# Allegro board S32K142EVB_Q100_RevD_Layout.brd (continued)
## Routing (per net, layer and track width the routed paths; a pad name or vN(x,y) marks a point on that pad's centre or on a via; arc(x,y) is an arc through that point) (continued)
P3V3: length 28.6
  TOP w0.381: 42.32,31.17 C24.1 ; C24.1 42.32,30.53 ; C24.1 44.23,30.53 ; C24.1 44.23,31.17 ; C24.1 43.27,31.17 ; U15.5 39.68,34.61 ; U15.5 38.99,34.08 ; U15.5 38.99,35.15 ; J10.1 40.65,29.57 ; J10.1 39.57,28.49 ; J10.1 39.57,30.65 ; 40.09,34.71 C548.1 ; C548.1 40.18,34.29 ; C548.1 41.11,34.71 ; TS5.1 45.3,32.42 ; TS5.1 41.49,32.42 ; TS5.1 43.4,31.34 ; TS5.1 43.4,33.5
  TOP w0.635: TP510.1 J3.7
  L3_MIX w0.508: 34.74,4.34 J3.7 ; J3.7 36.3,5.9 ; J3.7 34.51,5.12 ; J3.7 34.74,5.9 ; J3.7 36.3,4.34 ; J3.7 35.52,6.13 ; 40.65,29.57 J10.1 39.57,28.49
P3V3_SDA: length 32.6
  TOP w0.178: U9.5 33.64,39.65 v1(33.64,39.64)
  TOP w0.203: R607.1 v1(8.72,53.38)
  TOP w0.254: U2.7 28.45,46.1 v1(28.2,45.85) 28.54,45.51 U4.1 ; 15.64,40.52 16.01,40.88 16.58,40.88 16.94,40.52 ; U8.1 v1(19.51,43.09) ; v1(30.04,45.2) 30.3,45.46 R15.1 ; U7.1 28.13,41.66 27.86,41.93 v1(27.83,41.93) ; 30.5,36.03 C19.1 31.01,35.52 ; v1(15.03,27.14) 14.52,27.14 14.44,27.06 R77.1 ; U1.1 9.04,50.33 ; C18.1 30.44,35.34 ; U8.11 v1(16.65,37.9) ; R1.2 v1(6.4,52.28) ; 9.19,49.94 C3.1 ; U10.1 v1(27.41,38.62) ; 30.51,37.11 R52.1 ; C26.1 17.92,28.09 J12.1 ; 9.19,50.89 R3.1
  TOP w0.508: 15.64,40.52 C12.1 13.52,40.52 13.17,40.17 R627.2 v1(12.41,39.29) ; R30.1 30.95,42.34 30.92,42.37 30.92,42.95 v1(30.91,42.95) ; R42.1 R39.2 37.61,41.46 C10.1 v1(37.61,42.64) ; R12.1 v1(25.56,46.72) ; R60.1 v1(11.75,37.33)
  TOP w0.635: v1(19.51,43.09) 18.65,43.95 C7.1 17.76,44.83 C6.1
  BOTTOM w0.254: 17.32,27.37 J12.1 18.65,28.09
  vias: v1(8.85,50.86) v1(30.38,36.71)
P5V0: length 134
  TOP w0.457: R56.1 44.41,12.36 TP509.1
  TOP w0.584: R95.2 R96.2 R97.2
  TOP w0.635: C22.1 C550.1 ; C22.1 34.76,35.09 35.78,36.11 R624.1 ; C22.1 R169.1 32.84,33.69 32.41,33.26 C21.1 28.46,33.26 TP527.1 ; v1(115.66,26.58) 116.8,25.44 116.8,21.37 119.34,18.83 R95.2
  L3_MIX w0.381: TP527.1 28.41,34.66 ; TP527.1 29.43,34.33 ; TP527.1 29.43,32.3 ; TP527.1 28.41,31.97 ; TP527.1 27.39,34.33 ; TP527.1 29.76,33.31 ; J10.3 34.49,30.65 ; J10.3 33.66,28.74 ; J10.3 33.66,30.39 ; J10.3 33.41,29.57 ; J3.9 38.84,4.34 ; J3.9 38.06,6.13 ; J3.9 39.08,5.12 ; J3.9 38.84,5.9
  BOTTOM w0.635: 28.41,31.97 TP527.1 29.76,33.31 ; 25.24,28.49 J107.2 ; J107.2 24.16,29.57 ; J107.2 25.24,30.65 ; J107.2 26.32,29.57 ; 33.41,29.57 J10.3 ; J10.3 34.49,28.49 ; J10.3 35.57,29.57 ; J10.3 34.49,30.65 ; 41.87,32.04 44.41,32.04 45.68,30.77 45.68,28.61 46.44,27.85 57.24,27.85 57.87,27.22 63.21,27.22 63.91,27.91 67.34,27.91 67.91,27.34 76.16,27.34 77.43,28.61 92.67,28.61 94.7,26.58 v1(115.66,26.58)
  vias: v1(40.6,25.9) v1(44.28,11.98)
P5V0_SDA_USB_CONN_VBUS: length 5.6
  TOP w0.152: 8.02,40.99 D17.2 7.34,41.45 7.34,41.44
  TOP w0.356: 5.64,42.72 J7.1
  TOP w0.381: L1.1 8.02,40.99
  TOP w0.635: 7.34,41.44 6.92,41.44 5.64,42.72
P5V_SBC: length 85.9
  TOP w0.203: U33.1 v1(47.97,22.52) R617.1 ; v1(37.3,19.6) R621.1 U34.1 ; 42.89,22.64 43.01,22.52 U32.1
  TOP w0.254: R622.1 41.74,17.7 v1(42.13,18.08) R576.1 ; 42.38,21.88 R562.1 ; R562.1 42.89,22.39 ; R562.1 41.87,22.39 ; 41.24,22.26 41.24,22.77 ; 41.24,22.77 41.75,22.77 ; 41.24,22.77 40.73,22.77 ; 36.41,24.93 R619.1 ; R619.1 37.43,24.93 ; R619.1 36.92,25.44 ; 42,24.55 R572.1 ; 37.62,24.68 U26.1 ; 21.57,17.74 U19.5
  TOP w0.305: R536.1 v1(12.53,21.63) ; v1(20.66,14.57) 21.09,14.14 C27.1 21.98,15.18 22.82,16.01 C547.1 21.62,17.69 21.57,17.74
  TOP w0.508: TP525.1 53.05,21.12 R618.1 ; TP525.1 R571.1 TS8.1 ; TP525.1 v1(52.03,21.5)
  TOP w0.635: J107.1 25.36,27.15 v1(25.36,22.66) 24.16,21.45 R535.1 22.14,21.45 R594.1
  L3_MIX w0.254: v1(43.01,21.76) 42.66,21.4 42.66,21.35 42.13,20.82 v1(42.13,18.08)
  L3_MIX w0.305: v1(12.53,21.63) 16.73,21.63 17.23,21.12 17.23,14.87 17.54,14.57 v1(20.66,14.57)
  L3_MIX w0.635: v1(25.36,22.66) 22.56,22.66 19.52,25.69 13.17,25.69 12.53,25.06 v1(12.53,21.63)
  BOTTOM w0.254: v1(42.13,18.08) 41.61,17.56 38.32,17.56 37.3,18.58 v1(37.3,19.6)
  BOTTOM w0.508: J107.1 28.86,29.57 ; J107.1 27.78,28.49 ; J107.1 27.78,30.65
  vias: v1(34.58,24.56)
P5V_SDA: length 24.5
  TOP w0.254: 22.16,45.36 R14.1 22.67,45.86 ; U8.6 16.74,41.43 v1(16.62,41.43)
  TOP w0.508: C15.1 7.5,37.47 7.18,37.79 v1(7.18,38.88) L1.2 ; R70.1 v1(8.14,31.06) ; C11.1 v1(9.35,38.48) ; R57.1 v1(26.57,37.38) ; U11.1 v1(8.08,31.93) ; C25.1 v1(8.15,29.82)
  L3_MIX w0.635: v1(16.62,41.43) v1(16.62,45.82)
  BOTTOM w0.254: v1(22.02,45.89) 22.47,45.44 22.47,39.84 23.1,39.21 24.74,39.21 25.5,38.45 25.53,38.45 25.9,38.08 25.9,38.05 v1(26.57,37.38)
  vias: v1(7.36,46.09) v1(8.23,46.11) v1(9.16,46.11)
P5V_SDA_PSW: length 26.3
  TOP w0.584: U11.6 8.08,34.7 7.84,34.46 v1(6.95,34.46)
  BOTTOM w0.584: J107.3 19.08,25.95 9.49,25.95 6.95,28.49 v1(6.95,34.46)
VBATT: length 94.6
  TOP w0.254: D9.A 28.75,13.22 ; D9.A 28.75,10.73 ; D9.A 29.64,11.98 ; D9.A 27.86,11.98 ; C544.1 25.87,10.07 ; C544.1 25.87,9.05 ; C544.1 25.36,9.56 ; J3.1 27.9,6.13 ; J3.1 28.92,5.12 ; J3.1 26.89,5.12 ; J16.1 22.29,11.8 ; J16.1 22.29,7.96 ; J16.1 23.2,9.88 ; 24.85,12.99 TP522.1 ; TP522.1 26.89,12.99 ; TP522.1 26.89,10.96 ; TP522.1 25.87,13.32 ; TP522.1 24.85,10.96 ; TP522.1 25.87,10.63 ; TP522.1 24.52,11.98 ; TP522.1 27.22,11.98
  TOP w0.635: J3.15 TP507.1 44.41,8.29 43.01,9.69 30.44,9.69 29.81,10.33 ; R606.2 v1(9.61,18.2)
  L3_MIX w1.016: v1(9.61,18.2) 5.8,14.38 5.42,14.38 v1(4.79,13.75)
  BOTTOM w1.016: v3(23.93,7.2) 12.91,7.2 11.23,8.89 9.65,8.89 v1(4.79,13.75) 4.79,31.31 J11.2
VDD: length 85.1
  TOP w0.381: TPAD99.1 47.65,26.84 ; TPAD99.1 47.55,27.3 ; TPAD99.1 46.51,26.84 ; TPAD99.1 46.61,26.37 ; TPAD99.1 46.61,27.3 ; TPAD99.1 47.08,26.26 ; TPAD99.1 47.55,26.37 ; TPAD99.1 47.08,27.41 ; TP511.1 54.15,32.89 ; TP511.1 53.22,31.96 ; TP511.1 53.11,32.42 ; TP511.1 53.68,33 ; TP511.1 54.25,32.42 ; TP511.1 53.22,32.89 ; 48.81,29.58 J15.2 ; J15.2 49.88,28.51 ; J15.2 49.88,30.64 ; J15.2 50.94,29.58 ; J14.1 54.49,39.29 ; J14.1 54.49,38.57 ; J14.1 53.16,38.57 ; 49.11,37.25 R121.1 ; R121.1 49.2,36.83 ; R121.1 49.62,36.74 ; R121.1 50.04,36.83 ; R121.1 50.13,37.25 ; 47.71,44.87 R623.1 ; R623.1 47.8,45.29 ; R623.1 48.22,44.36 ; R623.1 47.8,44.45 ; C552.1 53.17,37.38 ; C552.1 53.68,36.87 ; C552.1 53.6,36.44 ; C552.1 53.6,37.29 ; C552.1 53.17,36.36 ; 40.46,37.55 SH1.2 ; SH1.2 41.15,38.15 ; SH1.2 40.46,38.74 ; 47.8,46.31 R574.1 ; R574.1 47.8,45.46 ; R574.1 47.71,45.89 ; 50.7,33.44 TS1.1 ; TS1.1 52.86,33.44 ; TS1.1 51.78,31.53 ; TS1.1 51.78,35.34 ; TP9.1 44.48,36.83 ; TP9.1 42.12,37.85 ; TP9.1 44.15,37.85 ; TP9.1 43.13,38.18 ; TP9.1 41.79,36.83 ; 47.8,41.23 R573.1 ; R573.1 47.71,40.81 ; R573.1 47.8,40.38 ; R573.1 48.22,41.31
  TOP w0.406: 49.49,34.33 R593.1 50.25,33.57 ; 50.25,32.04 R117.1 49.49,31.28
  TOP w0.508: SW3.4 v1(124.13,19.63) ; SW3.2 v1(124.13,27.21) ; SW2.4 v1(124.13,30.97) ; SW2.2 v1(124.13,38.79)
  TOP w0.635: v1(45.68,14.64) 45.68,16.29 R604.1
  L3_MIX w0.508: 42.12,35.81 TP9.1 ; TP9.1 43.13,35.48 ; TP9.1 42.12,37.85 ; TP9.1 41.79,36.83 ; TP9.1 43.13,38.18 ; 35.95,29.57 J10.2 37.03,30.65
  L3_MIX w0.635: 47.97,2.96 47.97,6.52 45.55,8.93 45.55,11.09 45.68,11.21 v1(45.68,14.64)
  BOTTOM w0.381: 112.94,56.88 TP4.1 ; TP4.1 112.94,54.85 ; TP4.1 115.3,55.87 ; TP4.1 112.61,55.87 ; TP4.1 114.97,56.88 ; TP4.1 113.96,54.52 ; TP4.1 114.97,54.85
  vias: v1(69.96,3.11) v1(69.97,2.07) v1(69.94,1.09) v1(70.67,3.09) v1(70.66,2.06) v1(70.64,1.12)
VDD_MCU: length 63.8
  TOP w0.254: C140.1 64.61,33.06 ; C140.1 64.1,32.55 ; C140.1 63.59,33.06 ; C144.1 62.71,33.49 ; C144.1 62.71,32.85 ; C144.1 60.81,32.85 ; C144.1 61.76,32.85 ; U35.10 68.64,30.56 ; U35.10 68.64,30.66 ; U35.10 66.6,30.75 ; U35.10 66.6,30.66 ; U35.61 81.54,28.16 ; 59.27,35.47 R300.1 ; R300.1 59.27,34.84 ; R300.1 60.03,35.47 ; R300.1 60.8,34.84
  TOP w0.305: U35.87 v1(75.87,38.39) 75.87,38.94 C129.1 ; 84.59,28.31 84.24,28.31 84.09,28.16 U35.61 ; U35.38 75.37,19.88 v2(75.4,19.85)
  TOP w0.635: J15.1 47.34,31.28 47.97,31.92 R117.2 ; C133.1 76.42,41.19 75.65,40.42 C142.1 C129.1 ; TS2.1 75.65,15.53 C131.1 C141.1 75.65,19.6 v2(75.4,19.85) ; 81.54,28.16 v2(75.12,28.16) ; 84.59,28.31 C143.1 87.92,28.31 C146.1 88.1,28.49 TP533.1
  BOTTOM w0.508: v1(68.92,30.52) 67.53,31.92 v2(64.99,31.92)
  BOTTOM w0.635: v2(64.99,31.92) 64.35,31.28 49.04,31.28 J15.1
  vias: v2(75.12,30.66)
VDD_PERH: length 207.4
  TOP w0.16: R648.1 R647.1 90.51,43.42 84,49.94 84,50.75 82.38,52.36 82.38,54.78 J6.10 ; U32.8 43.88,23.69 v1(43.54,24.04)
  TOP w0.203: v1(38.27,19.85) 38.27,19.93 38.44,20.1 38.7,20.1 38.8,20 U34.8 ; R614.1 41.62,21.63 41.87,21.37 41.87,21.35 v1(41.93,21.35) ; R615.1 v1(37.44,21.63) ; v1(48.86,24.17) 49.06,24.17 49.47,23.75 U33.8 ; v1(37.55,26.2) 38.19,26.2 38.55,25.84 U26.8 ; R616.1 v1(43.27,26.71) 43.01,26.45 R612.1
  TOP w0.381: 53.56,12.8 TS6.1 ; TS6.1 53.56,14.96 ; TS6.1 51.65,13.88
  TOP w0.508: R610.1 47.84,24.55 48.22,24.17 v1(48.86,24.17) ; R610.1 47.08,24.93 46.7,25.31 R609.1 ; R610.1 47.84,25.63 49.05,26.84 51.55,26.84 51.9,26.48 R611.1
  TOP w0.635: v2(65.49,12.48) 60.03,12.48 59.02,13.5 v1(55.97,13.5) ; v1(48.09,34.71) 47.97,34.58 R593.2 ; v1(37.55,26.2) 36.66,26.2 36.41,26.45 R613.1 35.84,27.22 TP541.1 R570.1 R530.1 R538.1 v1(34.76,22.9) ; J3.3 30.44,6.64 30.24,6.85 C49.1
  L3_MIX w0.635: v2(65.49,12.48) 66.26,12.48 67.34,11.4 67.34,9.12 70.57,5.88 70.57,4.36 71.72,3.21 71.72,1.82 72.35,1.18 82.38,1.18 J5.10 ; v1(43.27,26.71) 43.27,24.31 v1(43.54,24.04) ; v1(48.86,24.17) 48.86,26.58 51.25,28.97 51.25,31.56 v1(48.09,34.71) ; J3.3 30.19,5.37 30.19,20.1 32.98,22.9 v1(34.76,22.9) ; v1(38.27,19.85) 38.27,20.99 37.64,21.63 v1(37.44,21.63) 37.44,23.55 37.55,23.66 v1(37.55,26.2) ; v1(55.33,20.99) 54.83,20.49 54.83,16.17 v1(55.97,15.02) v1(55.97,14.26) v1(55.97,13.5)
  BOTTOM w0.381: J5.10 84.8,2.58 ; J5.10 84.22,3.59 ; J5.10 84.56,3.36 ; J5.10 83.78,3.59 ; J5.10 82.77,2.14 ; J5.10 84.8,3.02 ; J5.10 83,3.36 ; J5.10 82.77,2.58 ; J6.10 82.02,55.14 ; J6.10 81.24,56.93 ; J6.10 80.46,55.14 ; J6.10 82.02,56.7 ; J6.10 82.26,55.92 ; J6.10 81.24,54.9 ; J6.10 80.8,54.9 ; J6.10 80.46,56.7 ; R13.1 120.84,49.8 ; R13.1 120.84,47.77 ; R13.1 121.85,48.78 ; R13.1 119.82,48.78 ; 104.48,54.44 TP526.1 ; TP526.1 104.48,57.14 ; TP526.1 105.5,56.81 ; TP526.1 103.47,54.78 ; TP526.1 103.47,56.81 ; TP526.1 103.14,55.79 ; TP526.1 105.83,55.79 ; TP526.1 105.5,54.78
  BOTTOM w0.508: v1(41.93,21.35) 38.57,21.35 38.29,21.63 v1(37.44,21.63) 36.99,22.08 36.99,22.19 36.28,22.9 v1(34.76,22.9)
  BOTTOM w0.635: v1(37.55,26.2) 38.95,24.8 41.36,24.8 41.49,24.93 42.9,24.93 43.54,24.3 v1(43.54,24.04) 44.23,24.04 44.36,24.17 v1(48.86,24.17) 53.15,24.17 55.33,21.98 v1(55.33,20.99)
VDDA: length 18.2
  TOP w0.305: U35.11 66.11,30.16
  TOP w0.381: 60.03,32.68 R300.2 59.27,33.31 ; C540.1 64.1,31.53 ; C540.1 63.59,32.04 ; C540.1 63.17,31.96 ; 58.84,33.31 L512.1 ; L512.1 58.42,33.4 ; L512.1 59.26,34.24 ; L512.1 58.33,33.82 ; L512.1 58.42,34.24 ; C543.1 61.3,32.04 ; C543.1 61.73,31.96 ; C543.1 60.88,31.96 ; C543.1 60.79,31.53 ; C539.1 58.71,31.34 ; C539.1 58.08,33.25 ; C539.1 58.71,32.3 ; 62.02,31.96 C541.1 ; C541.1 62.45,32.04 ; C541.1 62.87,31.96 ; 58.84,30.39 C542.1 58.84,31.34 ; 64.6,30.9 R628.1 65.37,30.9
  TOP w0.508: R628.1 65.48,30.16 66.11,30.16
ADC_POT: length 72.2
  TOP w0.16: C549.1 R597.2 TP528.1 115.02,48.55 99.15,48.55 97.5,46.9 v1(97.5,38.14) ; R164.1 v1(79.46,14.64) ; R665.1 v1(88.73,38.14)
  L3_MIX w0.16: v1(86.45,15.41) 86.45,21.95 86.83,22.33 86.83,23.44 87.21,23.82 87.21,24.42 88.35,25.57 88.35,26.07 87.46,26.96 87.46,36.87 v1(88.73,38.14)
  BOTTOM w0.16: v1(79.46,14.64) 82.13,14.64 82.89,15.41 v1(86.45,15.41) ; v1(97.5,38.14) v1(88.73,38.14)
AREF: length 57.4
  TOP w0.635: v1(58.76,43.35) 58.76,43.6 54.19,48.17 40.35,48.17 38.82,46.65 36.28,46.65 33.62,49.31 25.36,49.31 23.84,50.84 J2.15 ; R569.2 v1(59.54,29.25)
  L3_MIX w0.635: v1(58.76,43.35) 58.76,29.88 59.4,29.25 v1(59.54,29.25)
BTN0: length 47
  TOP w0.16: C16.1 119.63,31.03 R596.2 TP530.1 114.13,28.11 99.95,28.11 94.58,22.73 94.58,18.2 89.33,12.95 86.49,12.95 84.67,14.77 R152.1
BTN1: length 47.6
  TOP w0.16: C28.1 119.71,27.34 R595.2 TP529.1 100.04,27.34 95.21,22.52 95.21,16.8 91.02,12.61 85.94,12.61 R153.1
CAN_HI: length 23.4
  TOP w0.16: U19.18 14.82,16.74 v1(14.44,16.36) ; R92.1 TP504.1 ; R92.1 v1(8.85,23.28) ; R92.1 5.55,23.28 5.51,23.24 J13.1
  L3_MIX w0.16: v1(8.85,23.28) 9.36,23.28 11.9,20.74 15.46,20.74 16.47,19.72 16.47,17.82 15.01,16.36 v1(14.44,16.36)
CAN_LO: length 22.1
  TOP w0.16: J13.2 4.2,20.7 4.53,20.36 4.53,15.02 6.18,13.37 7.33,13.37 7.33,14.39 10.18,17.24 TP503.1 U19.17
JTAG_TCLK/SWD_CLK: length 59
  TOP w0.16: J14.4 50.54,40.56 49.76,39.79 R575.1 v1(49.24,39.03) ; v1(69.43,45.3) TP536.1 69.18,44.23 69.18,43.09 ; R626.1 v1(28.03,35.09)
  L3_MIX w0.16: v1(49.24,39.03) 49.24,36.87 v1(48.73,36.36)
  BOTTOM w0.16: v1(48.73,36.36) 46.06,36.36 43.65,38.77 41.36,38.77 38.82,36.23 34.25,36.23 33.11,35.09 v1(28.03,35.09) ; J14.4 50.52,40.56 50.25,40.3 50.25,39.2 51.29,38.16 55.99,38.16 61.85,44.03 68.72,44.03 69.43,44.74 v1(69.43,45.3)
JTAG_TDI: length 30.1
  TOP w0.16: J14.8 51,43.1 R623.2 ; 71.21,43.09 71.21,44.36 TP538.1 v1(71.08,45.38)
  BOTTOM w0.16: J14.8 50.75,43.1 50.38,43.47 50.38,44.87 51.4,45.89 70.57,45.89 v1(71.08,45.38)
JTAG_TDO: length 34.8
  TOP w0.16: J14.6 50.27,41.83 R573.2 ; v1(73.37,45.3) 73.37,44.53 TP537.1 73.24,44.4 73.24,43.09
  BOTTOM w0.16: v1(73.37,45.3) 72.4,46.27 51.27,46.27 49.62,44.62 49.62,42.58 50.37,41.83 J14.6
JTAG_TMS/SWD_DIO_PTA4: length 45.6
  TOP w0.16: J14.2 51.28,39.29 50.25,38.27 R121.2 v1(48.7,38.27) ; 67.91,43.09 67.91,44.36 TP535.1 v1(66.97,44.49) ; v1(34.12,47.54) 33.74,47.92 R625.1
  BOTTOM w0.16: J14.2 52.68,38.5 55.83,38.5 61.56,44.23 61.58,44.23 61.71,44.36 66.84,44.36 v1(66.97,44.49) ; v1(48.7,38.27) 47.71,38.27 42.51,43.47 34.89,43.47 33.62,44.74 33.62,47.03 v1(34.12,47.54)
LEDRGB_BLUE: length 4.4
  TOP w0.16: Q8.3 118.75,7.4 118.83,7.48 TP28.1 D11.C3
LEDRGB_GREEN: length 7.5
  TOP w0.16: Q7.3 118.9,4.86 TP29.1 D11.C2
LEDRGB_RED: length 10.6
  TOP w0.16: Q6.3 118.71,2.58 TP30.1 D11.C1
LIN: length 34.1
  TOP w0.406: U21.6 14.46,25.43 13.18,26.71 TS4.1 11.14,25.9 R171.1 R80.1 8.6,24.75 7.92,25.43 TP18.1 5.51,26.03 C17.1 J11.1
LIN_RX: length 89.8
  TOP w0.16: v1(71.21,18.96) 70.7,18.45 R650.2 ; R538.2 31.44,22.9 31.44,22.89 v1(31.2,22.89) U21.1 ; R130.1 TP519.1 v1(68.54,12.74) 70.45,12.74 70.7,12.48 72.48,12.48 73.2,11.76 85.33,11.76 85.66,11.43 v1(86.19,11.43) ; R667.1 v1(88.61,23.03)
  L3_MIX w0.16: v1(88.61,23.03) 87.34,21.76 87.34,15.02 86.19,13.88 v1(86.19,11.43) ; v1(66.76,20.87) 67.4,20.87 69.3,18.96 v1(71.21,18.96) 68.54,16.29 v1(68.54,12.74)
  BOTTOM w0.16: v1(66.76,20.87) 66.76,20.45 65.82,19.51 59.6,19.51 58.92,20.19 51.31,20.19 50.38,21.12 42.89,21.12 42.13,21.88 38.82,21.88 37.3,23.41 36.5,23.41 36.5,23.41 34.55,23.41 34.54,23.41 31.72,23.41 v1(31.2,22.89)
LIN_SLP: length 52.8
  TOP w0.16: R529.2 61.19,18.45 TP521.1 50.84,17.26 ; R530.2 31.44,24.42 v1(31.18,24.16) U21.2
  TOP w0.203: 50.84,17.26 50.51,16.93 49.75,16.93 48.86,17.82 v1(48.37,17.82)
  L3_MIX w0.203: v1(31.18,24.16) 30.44,24.16 24.73,18.45 v1(24.73,18.2)
  BOTTOM w0.203: v1(48.37,17.82) 46.85,16.29 37.55,16.29 35.52,18.33 25.34,18.33 25.21,18.2 v1(24.73,18.2)
LIN_TX: length 88
  TOP w0.16: U21.4 v1(31.2,26.7) 31.44,26.7 31.44,26.71 R570.2 ; v1(87.21,10.71) 86.87,10.37 78.11,10.37 77.39,11.08 76.45,11.08 76.08,10.7 69.18,10.7 v1(67.14,12.74) 66.51,13.37 TP520.1 R131.1 ; R668.1 v1(88.61,20.74) ; R652.2 v1(68.8,18.33)
  L3_MIX w0.16: v1(88.61,20.74) 88.1,20.23 88.1,14.39 87.72,14.01 87.72,13.25 87.21,12.74 v1(87.21,10.71) ; v1(67.14,12.74) 67.14,16.04 68.8,17.69 v1(68.8,18.33) 67.15,19.97 v1(65.63,19.97)
  BOTTOM w0.16: v1(65.63,19.97) 60.37,19.97 55.45,24.89 45.8,24.89 45.79,24.89 44.81,24.89 44.81,24.89 43.88,24.89 43.48,25.28 43.48,25.29 43.26,25.51 41.18,25.51 41.11,25.44 39.13,25.44 37.79,26.78 37.32,26.78 37.24,26.7 v1(31.2,26.7)
LVLRST_EN: length 2.1
  TOP w0.203: U1.5 5.95,50.33 5.57,50.71 R1.1
MIC2005_CSLEW: length 1.8
  TOP w0.16: U11.5 C15.2
POWER_EN: length 15.7
  TOP w0.16: R69.1 v1(12.64,32.91) ; U8.31 20.95,42.91 v1(20.95,42.96)
  BOTTOM w0.16: v1(12.64,32.91) 12.64,34.08 15.65,37.09 15.65,38.42 16.73,39.5 17.25,39.5 20.38,42.63 20.63,42.63 v1(20.95,42.96)
PTA0: length 50.6
  TOP w0.16: v1(87.73,41.81) 87.73,40.69 86.58,39.54 84.87,39.54 84.65,39.31 82.41,39.31 81.84,38.73 80.57,38.73 79.87,38.04 U35.79
  L3_MIX w0.16: J5.7 82.19,6.06 82.19,6.85 85.18,9.85 85.18,16.48 85.85,17.16 85.85,23.45 86.45,24.04 86.45,38.38 86.65,38.57 86.86,38.79 86.86,40.95 v1(87.73,41.81)
PTA1: length 40.8
  TOP w0.16: R666.1 v1(88.73,39.15)
  L3_MIX w0.16: v1(86.07,38.65) 86.07,37.39 85.48,36.81 85.48,35.62 85.69,35.41 85.69,24.34 85.18,23.84 85.18,17.44 84.5,16.76 84.5,10.15 81.62,7.28 80.86,7.28 J5.5
  BOTTOM w0.16: v1(86.07,38.65) 86.58,39.15 v1(88.73,39.15)
PTA2: length 6.3
  TOP w0.16: U35.73 85.26,34.16 86.19,35.09 R644.1 R542.2 R540.1
PTA3: length 9
  TOP w0.16: U35.72 85.3,33.66 86.11,34.47 88.88,34.47 89.5,35.09 89.5,37.12
PTA4: length 1
  TOP w0.16: R546.1 66.89,43.09
PTA6: length 4.4
  TOP w0.16: U35.58 84.09,26.66 85.69,25.06 R147.1
PTA7: length 31.3
  TOP w0.16: U35.57 83.91,26.16 v1(84.42,25.65)
  L3_MIX w0.16: J5.9 85.36,6.7 86,6.7 89.04,9.74 89.04,11.61 89.99,12.57 89.99,13.57 90.08,13.66 90.08,15.98 89.95,16.11 89.95,25.64 v1(90,25.69)
  BOTTOM w0.16: v1(90,25.69) 89.37,26.33 85.1,26.33 v1(84.42,25.65)
PTA8: length 18.1
  TOP w0.16: U35.100 v1(69.37,38.38)
  L3_MIX w0.16: v1(69.37,38.38) 69.37,38.83 68.29,39.92 68.29,43.47 69.05,44.23 69.05,45.03 68.97,45.11 68.97,47.84 71.08,49.95 J6.17
PTA9: length 20.1
  TOP w0.16: U35.99 v1(69.87,35.64)
  L3_MIX w0.16: v1(69.87,35.64) 69.87,37.19 68.91,38.15 68.91,38.79 67.91,39.79 67.91,44.74 68.54,45.38 J6.19
PTA10: length 1
  TOP w0.16: 74.26,43.09 R545.1
PTA11: length 33.5
  TOP w0.16: U35.91 73.87,38.02 73.41,38.48 73.41,39.07 73.41,39.07 73.41,39.09 73.68,39.36 73.7,39.36 73.87,39.53 v1(73.87,41.19)
  L3_MIX w0.16: J1.2 62.17,54.63 62.17,51.98 61.56,51.37 v1(61.56,41.06)
  BOTTOM w0.16: v1(61.56,41.06) 62.19,41.69 71.57,41.69 72.1,41.17 72.1,41.17 72.54,40.73 73.41,40.73 v1(73.87,41.19)
PTA12: length 21.6
  TOP w0.16: U35.90 74.37,38.15 73.88,38.65 v1(73.88,38.9)
  L3_MIX w0.16: v1(73.88,38.9) 74.37,39.39 74.37,43.71 75.48,44.82 75.48,49.36 72.53,52.32 72.53,54.82 J6.16
PTA13: length 20.3
  TOP w0.16: v1(74.76,38.39) 74.87,38.29 U35.89
  L3_MIX w0.16: v1(74.76,38.39) 74.76,43.47 75.82,44.52 75.82,51.66 75.07,52.42 75.07,54.82 J6.14
PTA14: length 67
  TOP w0.16: v1(75.02,47.54) 75.8,46.76 75.8,41.43 75.02,40.65 75.02,38.9 75.37,38.55 U35.88
  BOTTOM w0.16: v1(75.02,47.54) 64.48,47.54 63.38,48.64 53.41,48.64 52.18,49.86 39.74,49.86 38.72,50.88 27.33,50.88 25.14,53.06 25.14,54.62 J2.16
PTA15: length 7.4
  TOP w0.16: R167.1 81.57,41.56 81.57,40.38 81.3,40.11 79.86,40.11 77.87,38.12 U35.83
PTA16: length 7.6
  TOP w0.16: U35.82 78.37,38.06 80.08,39.77 81.44,39.77 82.77,41.1 82.77,41.59 R165.1
PTA17: length 54.1
  TOP w0.16: U35.62 82.07,28.66 v1(81.03,29.69)
  L3_MIX w0.16: J1.4 59.63,54.63 59.63,52.73 58,51.09 58,29.5 59.02,28.49 v1(59.52,28.49)
  BOTTOM w0.16: v1(81.03,29.69) 60.73,29.69 v1(59.52,28.49)
PTB0: length 50.8
  TOP w0.16: J4.5 61.47,10.75 68.63,10.75 69.01,10.37 76.22,10.37 76.59,10.74 77.25,10.74 77.97,10.03 87.25,10.03 v1(87.59,9.69) ; R670.1 v1(88.61,24.04)
  L3_MIX w0.16: v1(87.59,9.69) 87.79,9.89 87.79,12.56 88.1,12.87 88.1,13.88 88.48,14.26 88.48,19.85 89.12,20.49 89.12,23.53 v1(88.61,24.04)
PTB1: length 45.4
  TOP w0.16: R669.1 v1(88.61,21.76) ; J4.7 63.67,10.41 68.49,10.41 68.87,10.03 76.36,10.03 76.73,10.41 77.11,10.41 77.83,9.69 85.68,9.69 v1(86.32,9.05)
  L3_MIX w0.16: v1(88.61,21.76) 87.72,20.87 87.72,14.77 86.7,13.75 86.7,13.61 86.7,13.6 86.7,13.22 86.7,13.22 86.7,11.21 86.32,10.83 v1(86.32,9.05)
PTB2: length 83.8
  TOP w0.16: v1(79.51,48.51) 79.12,48.91 72.66,48.91 72.04,49.52 39.36,49.52 38.34,50.54 31.76,50.54 J2.11 ; U35.48 v1(80.37,19.63)
  L3_MIX w0.16: v1(80.37,19.63) 80.37,23.68 79.8,24.25 79.8,28.88 79.31,29.37 79.31,46.74 79.51,46.94 v1(79.51,48.51)
PTB3: length 78.1
  TOP w0.16: v1(78.96,50.2) 39.64,50.2 38.62,51.22 33.62,51.22 J2.9 ; U35.47 79.89,21.42 v1(79.89,22.84)
  L3_MIX w0.16: v1(78.96,50.2) 78.83,50.08 78.83,47.9 78.97,47.76 78.97,29.23 79.46,28.74 79.46,23.27 v1(79.89,22.84)
PTB4: length 66.7
  TOP w0.16: J2.7 35.48,51.89 38.9,51.89 39.92,50.88 67.57,50.88 v1(67.78,51.09) ; v1(69.06,24.9) 70.37,23.59 U35.28
  L3_MIX w0.16: v1(67.78,51.09) 67.78,45.12 67.5,44.84 67.5,39.69 68.54,38.65 68.54,38.01 69.41,37.14 69.41,35.11 70.02,34.5 70.02,25.85 v1(69.06,24.9)
PTB5: length 75.1
  TOP w0.16: v1(63.21,16.04) 63.21,16.68 64.48,17.95 65.87,17.95 67.69,19.76 69.45,19.76 69.87,20.18 U35.27
  L3_MIX w0.16: v1(43.9,13.37) 44.16,13.63 44.16,25.68 43.95,25.88 43.95,29.67 44.58,30.31 44.58,32.69 44.58,32.69 44.58,32.76 45.43,33.6 45.43,44.49 J2.5
  BOTTOM w0.16: v1(63.21,16.04) 62.32,15.15 59.4,15.15 57.29,13.04 44.24,13.04 v1(43.9,13.37)
PTB6: length 6.4
  TOP w0.16: R81.1 R84.1 63.32,25.95 65.03,27.66 U35.16
PTB6_XTAL: length 7.2
  TOP w0.16: Y3.2 57.48,25.58 C127.1 58.76,25.06 59.52,25.82 R91.2 60.29,25.82 60.54,26.07 61.81,26.07 R84.2
PTB7: length 6.2
  TOP w0.16: R90.1 R88.1 63.72,26.96 64.84,28.09 65.76,28.09 65.83,28.16 U35.15
PTB7_EXTAL: length 7.2
  TOP w0.16: R88.2 61.18,26.96 60.79,27.34 R91.1 59.52,27.34 58.76,28.11 C126.1 57.48,27.58 Y3.1
PTB8: length 44.7
  TOP w0.16: U35.77 80.87,37.72 81.16,38.01 83.53,38.01 83.91,38.39 84.54,38.39 84.54,38.39 v1(84.54,38.39)
  L3_MIX w0.16: v1(85.21,49.6) 85.21,44.79 84.89,44.47 84.89,38.73 v1(84.54,38.39)
  BOTTOM w0.16: v1(85.21,49.6) 75.5,49.6 74.51,50.58 61.9,50.58 60.37,52.12 59.64,52.12 J1.5
PTB9: length 46.6
  TOP w0.16: v1(84.22,36.54) 83.86,36.91 U35.76
  L3_MIX w0.16: v1(84.41,48.88) 83.78,48.26 83.78,44.1 84.54,43.35 84.54,39.15 84.08,38.69 84.08,38.2 84.22,38.06 v1(84.22,36.54)
  BOTTOM w0.16: J1.7 59.02,50.2 74.41,50.2 75.36,49.26 84.03,49.26 v1(84.41,48.88)
PTB10: length 48.8
  TOP w0.16: v1(83.12,35.85) 83.02,35.85 83.12,35.75 U35.75
  L3_MIX w0.16: v1(55.08,34.96) 55.08,34.96 55.08,34.97 55.08,47.85 53.3,49.63 J1.9
  BOTTOM w0.16: v1(55.08,34.96) 55.08,34.96 55.08,34.96 55.24,34.8 63.43,34.8 64.82,36.2 82.78,36.2 v1(83.12,35.85)
PTB11: length 55.8
  TOP w0.16: U35.74 v1(84.49,34.66)
  L3_MIX w0.16: J1.11 50.76,50.04 54.62,46.18 54.62,34.77 54.89,34.5 54.91,34.5 54.94,34.46 v1(54.94,32.27)
  BOTTOM w0.16: v1(54.94,32.27) 63.85,32.27 66.75,35.18 70.15,35.18 70.83,35.86 79.76,35.86 80.15,35.47 81.86,35.47 82.68,34.66 v1(84.49,34.66)
PTB12: length 81.8
  TOP w0.16: v1(92.42,34.2) 91.67,33.46 86.74,33.46 84.94,31.66 U35.68
  L3_MIX w0.16: J4.3 53.05,5.37 53.05,21.28 53.26,21.49 53.26,22.09 54.32,23.15 54.32,29.91 54.15,30.07 54.15,30.43 54.32,30.6 54.32,34.6 54.06,34.85 v1(54.06,35.9)
  BOTTOM w0.16: v1(92.42,34.2) 92.29,34.07 88.51,34.07 86.86,35.73 83.91,35.73 83.1,36.53 64.14,36.53 63.78,36.17 63.78,36.15 63.48,35.85 63.06,35.85 63.01,35.9 v1(54.06,35.9)
PTB13: length 40.1
  TOP w0.16: U35.67 v1(84.41,31.16)
  L3_MIX w0.16: J5.11 86.32,6.01 87.21,6.9 87.72,6.9 90.77,9.95 90.77,11.81 92.72,13.75 92.72,17.32 92.72,17.33 92.72,17.61 93.31,18.2 93.31,30.9 v1(93.69,31.28)
  BOTTOM w0.16: v1(93.69,31.28) 87.72,31.28 87.59,31.16 v1(84.41,31.16)
PTB14: length 58.3
  TOP w0.16: R637.1 v1(88.73,32.93)
  L3_MIX w0.16: v1(88.73,32.93) 88.23,32.42 88.23,27.22 89.12,26.33 89.12,24.85 88.77,24.5 88.37,24.5 87.17,23.3 87.17,22.19 86.91,21.93 86.91,15.21 85.69,13.99 85.69,9.44 v1(85.31,9.06)
  BOTTOM w0.16: J4.8 59.52,3.72 59.52,6.39 60.43,7.29 64.68,7.29 65.28,7.89 73.92,7.89 74.74,8.71 76.99,8.71 77.34,9.06 77.37,9.06 77.49,9.18 83.55,9.18 83.67,9.06 v1(85.31,9.06)
PTB15: length 58.7
  TOP w0.16: R638.1 v1(91.27,32.93)
  L3_MIX w0.16: v1(90.31,10.58) 90.39,10.65 90.39,11.98 92.29,13.88 92.29,29.16 92.41,29.29 92.41,31.79 v1(91.27,32.93)
  BOTTOM w0.16: v1(90.31,10.58) 88.28,8.55 83.7,8.55 83.41,8.84 77.63,8.84 77.16,8.38 74.88,8.38 74.06,7.55 65.42,7.55 64.82,6.95 63.26,6.95 62.32,6.01 62.32,3.85 61.05,2.58 J4.10
PTB16: length 53
  TOP w0.16: R640.1 v1(88.73,30.77)
  L3_MIX w0.16: v1(84.04,7.74) 86.56,7.74 88.7,9.88 88.7,11.75 89.5,12.55 89.5,15.26 89.06,15.7 89.06,17.56 89.5,18 89.5,30.01 v1(88.73,30.77)
  BOTTOM w0.16: v1(84.04,7.74) 83.27,8.5 77.77,8.5 77.3,8.04 75.02,8.04 74.2,7.22 65.56,7.22 64.73,6.39 64.73,3.85 J4.12
PTB17: length 59.7
  TOP w0.16: R642.1 v1(91.27,29.76)
  L3_MIX w0.16: v1(89.5,10.58) 89.5,11.6 90.33,12.43 90.33,13.43 91.78,14.88 91.78,16.42 90.68,17.52 90.68,18.97 91.28,19.57 91.28,29.58 91.36,29.67 v1(91.27,29.76)
  BOTTOM w0.16: J4.6 56.98,3.72 56.98,5.5 59.19,7.71 64.09,7.71 64.14,7.65 64.56,7.65 64.61,7.71 64.62,7.71 65.14,8.23 73.78,8.23 74.6,9.05 76.85,9.05 77.32,9.52 84.86,9.52 85.54,10.2 89.12,10.2 v1(89.5,10.58)
PTC0: length 26.2
  TOP w0.16: R534.1 v1(95.77,14.49) ; R146.1 v1(77.43,17.69) 77.11,18.02 77.11,19.64 76.37,20.37 U35.40
  BOTTOM w0.16: v1(77.43,17.69) 78.24,16.89 93.98,16.89 95.77,15.1 v1(95.77,14.49)
PTC1: length 62.3
  TOP w0.16: v1(76.42,17.44) 76.42,19.76 75.87,20.31 U35.39 ; R172.2 96.67,32.86 96.67,32.86 R525.2 v1(95.65,32.01) ; v1(75.27,7.53) 75.86,6.94 88.09,6.94 88.86,6.16 J5.13
  L3_MIX w0.16: J5.13 88.86,6.9 89.44,7.48 89.68,7.48 91.11,8.91 91.11,11.67 93.05,13.61 93.05,17.18 93.69,17.82 93.69,30.05 v1(95.65,32.01) ; v1(75.27,7.53) 75.27,10.07 75.94,10.74 75.94,16.96 v1(76.42,17.44)
PTC2: length 40.8
  TOP w0.16: R636.1 67.53,13.1 69.59,11.04 75.94,11.04 76.32,11.42 83.59,11.42 83.67,11.34 85.27,11.34 85.65,10.96 86.57,10.96 86.95,11.34 v1(91.91,11.34) 92.06,11.19 R527.2 R528.2
  L3_MIX w0.16: J5.15 91.91,5.63 v1(91.91,11.34)
PTC3: length 49
  TOP w0.16: R533.1 v1(95.6,30.39) ; R664.1 63.97,16.55 v1(64.35,16.93) 64.78,17.36 R635.1 R132.2
  L3_MIX w0.16: v1(93.73,16.42) 93.73,17.23 94.2,17.69 94.2,28.99 v1(95.6,30.39)
  BOTTOM w0.16: v1(93.73,16.42) 64.86,16.42 v1(64.35,16.93)
PTC4: length 69.5
  TOP w0.16: 70.19,43.09 v1(70.19,43.98)
  L3_MIX w0.16: v1(70.57,11.77) 70.57,17.37 71.37,18.16 71.54,18.16 72.01,18.63 72.01,21.59 70.83,22.77 70.83,41.31 70.19,41.95 v1(70.19,43.98)
  BOTTOM w0.16: v1(70.57,11.77) 69.18,11.77 68.96,11.55 66.99,11.55 66.45,11.01 58.91,11.01 58.65,10.75 51.86,10.75 47.71,6.6 42.72,6.6 41.74,5.63 41.74,3.59 40.73,2.58 J3.12
PTC5: length 74.1
  TOP w0.16: 72.22,43.09 v1(72.22,43.98)
  L3_MIX w0.16: v1(72.1,11.77) 72.1,12.55 72.57,13.02 72.57,17.78 73.37,18.58 73.37,23.15 72.39,24.13 72.39,35.49 72.22,35.65 v1(72.22,43.98)
  BOTTOM w0.16: v1(72.1,11.77) 71.51,12.36 69.29,12.36 68.82,11.89 66.79,11.89 66.71,11.98 65.71,11.98 65.71,11.97 65.28,11.97 64.9,12.36 59.78,12.36 58.51,11.09 51.72,11.09 47.57,6.94 40.22,6.94 39.2,5.92 39.2,3.72 J3.10
PTC6: length 64.2
  TOP w0.16: R630.1 v1(83.54,40.17)
  L3_MIX w0.16: v1(80.73,10.96) 83.36,13.59 83.36,34.62 82.66,35.32 82.66,39.3 83.53,40.17 v1(83.54,40.17)
  BOTTOM w0.16: J4.4 53.43,2.58 54.7,3.85 54.7,5.88 58.17,9.35 62.94,9.35 63.22,9.35 63.69,9.82 75.5,9.82 77.08,11.4 80.3,11.4 v1(80.73,10.96)
PTC7: length 69.8
  TOP w0.16: R632.1 v1(86.4,40.17)
  L3_MIX w0.16: v1(86.4,40.17) 85.61,39.38 85.61,37.41 85.14,36.95 85.14,35.48 85.35,35.27 85.35,24.48 84.62,23.75 84.62,21.63 84.16,21.17 84.16,18.09 84.5,17.76 84.5,17.37 84.16,17.04 84.16,11.72 v1(83.4,10.96)
  BOTTOM w0.16: v1(83.4,10.96) 82.57,11.79 77,11.79 75.36,10.16 63.55,10.16 63.08,9.69 55.97,9.69 52.03,5.75 52.03,3.85 J4.2
PTC8: length 31
  TOP w0.16: U35.56 v1(80.59,25.66)
  L3_MIX w0.16: J6.9 80.18,52.31 80.18,47.84 80.64,47.37 80.64,34.42 80.69,34.37 80.69,33.81 80.57,33.69 80.57,26.14 80.59,26.12 v1(80.59,25.66)
PTC9: length 33.6
  TOP w0.16: v1(78.4,25.97) 79.16,25.97 79.97,25.16 U35.55
  L3_MIX w0.16: v1(78.4,25.97) 78.84,26.4 78.84,28.73 78.63,28.94 78.63,46.46 77.62,47.48 77.62,52.29 J6.11
PTC10: length 9.5
  TOP w0.16: U35.52 84.15,23.66 84.63,23.18 v1(84.63,20.76) 84.63,19.09 87.16,16.56 R133.2
PTC11: length 11.9
  TOP w0.16: U35.51 83.12,19.76 85.58,17.3 85.58,15.51 86.34,14.76 R134.2 v1(87.16,13.41)
PTC12: length 94.2
  TOP w0.16: v1(81.62,50.2) 79.61,50.2 79.15,50.66 78.76,50.66 78.64,50.54 39.78,50.54 38.76,51.55 33.79,51.55 32.6,52.74 32.6,54.78 J2.10 ; U35.50 81.37,20.13 83.98,17.52 84,17.52 v1(84.04,17.56) 84.67,16.93 R152.2
  L3_MIX w0.16: v1(84.04,17.56) 83.7,17.9 83.7,38.82 84.21,39.32 84.21,43.21 83.45,43.96 83.45,47.74 81.65,49.53 81.65,50.17 v1(81.62,50.2)
PTC13: length 94.2
  TOP w0.16: R153.2 v1(82.13,17.44) 82.13,18.35 80.87,19.61 U35.49 ; J2.12 30.18,54.66 30.18,52.63 31.93,50.88 38.48,50.88 39.5,49.86 72.18,49.86 72.8,49.24 80.49,49.24 v1(81.53,48.21)
  L3_MIX w0.16: v1(82.13,17.44) 82.65,17.96 82.65,34.37 81.98,35.04 81.98,47.76 v1(81.53,48.21)
PTC14: length 28.2
  TOP w0.16: R629.1 v1(78.45,14.77)
  L3_MIX w0.16: J4.14 66,2.71 67.09,3.79 67.09,6.48 65.75,7.82 65.75,10.83 64.73,11.85 64.73,12.86 64.22,13.36 v1(64.22,13.36)
  BOTTOM w0.16: v1(64.22,13.36) 64.22,13.36 64.22,13.37 68.8,13.37 69.05,13.12 74.26,13.12 75.91,14.77 v1(78.45,14.77)
PTC15: length 35.7
  TOP w0.16: v1(78.32,7.53) 78.57,7.28 93.33,7.28 95.03,5.58 95.03,4.03 J5.20 ; U35.45 v1(78.87,18.37)
  L3_MIX w0.16: v1(78.32,7.53) 78.3,7.55 78.3,13.97 78.91,14.58 78.91,14.96 78.3,15.57 78.3,17.8 v1(78.87,18.37)
PTC16: length 53.8
  TOP w0.16: v1(89.91,46.89) 89.91,47.38 85,52.29 85,54.7 J6.8 ; U35.44 v1(78.37,23.95)
  L3_MIX w0.16: v1(89.91,46.89) 90.65,46.89 93.18,44.36 93.18,32.68 92.8,32.3 v1(92.8,24.04)
  BOTTOM w0.16: v1(92.8,24.04) 92.34,24.5 85.64,24.5 85.18,24.04 78.46,24.04 v1(78.37,23.95)
PTC17: length 45.5
  TOP w0.16: v1(78.38,24.94) 77.87,24.43 U35.43
  L3_MIX w0.16: v1(87.85,25.82) 87.12,26.54 87.12,38.1 87.54,38.51 87.54,40.44 88.56,41.47 88.56,42.6 87.63,43.52 87.63,54.61 J6.6
  BOTTOM w0.16: v1(87.85,25.82) 85.31,25.82 84.93,25.44 84.93,25.44 84.63,25.14 84.62,25.14 84.43,24.94 v1(78.38,24.94)
PTD0: length 74.3
  TOP w0.16: R656.2 v1(67.02,40.93)
  L3_MIX w0.16: v1(67.02,40.93) 67.02,43.79 66.51,44.3 66.51,48.29 v1(66.89,48.68) ; v1(91.4,47.46) J6.1
  BOTTOM w0.16: J2.6 37.83,54.62 37.83,52.97 39.84,50.97 52.76,50.97 54.54,49.19 66.38,49.19 v1(66.89,48.68) 67.4,48.17 71.53,48.17 71.78,48.43 78.58,48.43 79.54,47.46 v1(91.4,47.46)
PTD1: length 49.3
  TOP w0.16: U35.3 v1(68.92,34.16)
  L3_MIX w0.16: J6.2 89.97,57.35 73.51,57.35 72.41,56.25 72.41,55.69 71.49,54.78 67.91,54.78 67.14,54 67.14,51.59 66.17,50.62 66.17,48.94 66.17,48.94 66.17,44.16 66.51,43.82 66.51,40.2 67.57,39.14 67.57,37.84 68.73,36.68 68.73,34.34 v1(68.92,34.16)
PTD2: length 29.3
  TOP w0.16: J6.3 88.86,51.47 92.04,48.3 92.04,35.2 90.97,34.13 86.25,34.13 85.28,33.16 U35.71
PTD3: length 72.8
  TOP w0.16: J6.4 87.59,57.19 75.13,57.19 75.13,57.19 49.5,57.19 J1.14 ; U35.70 v1(84.67,32.66)
  L3_MIX w0.16: v1(84.67,32.66) 84.97,32.95 84.97,35.17 84.8,35.34 84.8,37.09 85.22,37.5 85.22,43.26 86.62,44.66 86.62,47.27 86.62,50.75 85.24,52.13 85.24,56.37 85.87,57 87.78,57 J6.4
PTD4: length 85.6
  TOP w0.16: v1(92.67,35.22) 91.25,33.79 86.6,33.79 84.96,32.16 U35.69
  L3_MIX w0.16: v1(52.79,35.85) 52.79,35.58 53.97,34.4 53.97,30.73 53.81,30.57 53.81,29.93 53.97,29.77 53.97,23.44 52.92,22.39 52.92,21.63 50.76,19.47 J4.1
  BOTTOM w0.16: v1(92.67,35.22) 91.87,34.41 88.65,34.41 86.98,36.08 84.03,36.08 84.01,36.11 83.24,36.87 63.74,36.87 63.49,37.12 62.45,37.12 62.11,37.46 57.45,37.46 56.73,36.74 53.68,36.74 v1(52.79,35.85)
PTD5: length 52.4
  TOP w0.16: U35.33 v1(72.87,22.82)
  L3_MIX w0.16: v1(71.34,48.64) 71.72,48.26 71.72,35.68 72.05,35.35 72.05,23.64 v1(72.87,22.82)
  BOTTOM w0.16: v1(71.34,48.64) 67.82,48.64 66.93,49.52 55.46,49.52 52.05,52.93 52.05,54.63 J1.12
PTD6: length 36.4
  TOP w0.16: R649.2 70.7,13.88 71.34,13.25 72.87,13.25 73.04,13.08 78.11,13.08 78.7,12.48 85.56,12.48 85.81,12.23 94.7,12.23 v1(95.08,11.85)
  L3_MIX w0.16: J5.18 95.08,3.72 v1(95.08,11.85)
PTD7: length 34.8
  TOP w0.16: v1(92.67,11.72) 92.5,11.89 85.67,11.89 85.43,12.13 78.58,12.13 77.97,12.74 72.9,12.74 72.73,12.91 71.04,12.91 69.56,14.39 R651.2
  L3_MIX w0.16: v1(92.67,11.72) 92.67,3.85 J5.16
PTD8: length 49.6
  TOP w0.16: U35.42 77.37,22.82 77.38,22.83 77.38,23.45 v1(76.92,23.91) ; v1(89.74,45.94) 89.24,46.44 89.24,46.65 83.78,52.11 J6.7
  L3_MIX w0.16: v1(89.74,45.94) 89.83,45.85 89.83,43.19 89.42,42.77 89.42,42.39 89.54,42.27 89.54,31.59 90.48,30.65 90.48,29.43 90.6,29.3 90.6,23.66 v1(90.48,23.53)
  BOTTOM w0.16: v1(90.48,23.53) 85.76,23.53 85.61,23.68 78.75,23.68 78.56,23.49 77.35,23.49 v1(76.92,23.91)
PTD9: length 44
  TOP w0.16: v1(76.92,23.03) 76.92,22.56 76.87,22.51 U35.41
  L3_MIX w0.16: v1(86.32,22.47) 86.32,23.41 86.79,23.87 86.79,38.24 87.2,38.65 87.2,40.58 88.22,41.61 88.22,42.46 86.96,43.72 86.96,50.89 86.96,50.89 86.96,51.5 86.32,52.13 J6.5
  BOTTOM w0.16: v1(86.32,22.47) 86,22.8 85.91,22.8 85.37,23.34 78.89,23.34 78.57,23.03 v1(76.92,23.03)
PTD10: length 64.9
  TOP w0.16: U35.36 74.37,20.34 73.03,19 v1(73.03,17.56) 73.42,17.17 R166.1
  L3_MIX w0.16: J1.6 57.3,54.83 57.3,52.4 56.06,51.16 56.06,40.76 56.31,40.5 56.31,19 56.56,18.75 v1(56.56,15.87)
  BOTTOM w0.16: v1(56.56,15.87) 60.2,15.87 60.54,15.53 62.05,15.53 64.13,17.62 68.36,17.62 69,16.98 72.45,16.98 v1(73.03,17.56)
PTD11: length 66.7
  TOP w0.16: R168.1 71.97,17.19 v1(71.72,17.44) 71.92,17.64 71.92,18.42 73.87,20.37 U35.35
  L3_MIX w0.16: v1(53.81,15.91) 53.81,20.97 55.59,22.75 55.59,29.29 55.72,29.42 55.72,29.84 55.59,29.97 55.59,35.22 55.42,35.38 55.42,47.99 54.7,48.71 54.7,54.78 J1.8
  BOTTOM w0.16: v1(71.72,17.44) 71.72,17.44 71.13,17.44 71.12,17.44 69.03,17.44 68.4,18.07 61.43,18.07 59.74,16.38 54.43,16.38 54.29,16.24 54.14,16.24 v1(53.81,15.91)
PTD12: length 53
  TOP w0.16: U35.34 v1(73.37,24.01)
  L3_MIX w0.16: v1(73.37,24.01) 73.67,24.31 73.67,34.77 73.75,34.85 73.75,37.19 73.37,37.57 73.37,44.34 73.9,44.87 v1(73.9,49.71)
  BOTTOM w0.16: v1(73.9,49.71) 73.74,49.86 57.66,49.86 54.81,52.72 54.81,54.41 J1.10
PTD13: length 58.5
  TOP w0.16: v1(52.79,26.07) 52.79,24.68 53.56,23.91 58.67,23.91 60.16,22.42 60.16,20.49 60.85,19.79 63.41,19.79 66.77,23.16 U35.25
  L3_MIX w0.16: J2.1 41.62,49.57 46.11,45.08 46.11,33.33 45.26,32.48 45.26,27.81 v1(44.41,26.96)
  BOTTOM w0.16: v1(52.79,26.07) 52.33,26.53 45.6,26.53 45.17,26.96 v1(44.41,26.96)
PTD14: length 58.7
  TOP w0.16: v1(53.05,26.96) 53.56,26.45 53.56,24.55 53.85,24.25 58.81,24.25 60.54,22.52 60.54,20.61 60.92,20.23 63.21,20.23 66.63,23.66 U35.24
  L3_MIX w0.16: v1(44.41,29.38) 44.92,29.88 44.92,32.55 44.92,32.55 44.92,32.62 45.77,33.47 45.77,44.78 39.08,51.47 J2.3
  BOTTOM w0.16: v1(53.05,26.96) 45.68,26.96 44.41,28.23 v1(44.41,29.38)
PTD15: length 63.6
  TOP w0.16: R653.2 v1(61.05,21.88)
  L3_MIX w0.16: v1(61.05,21.88) 60.59,22.34 60.59,24.11 60.86,24.38 61.37,24.38 61.37,24.37 61.65,24.37 62.23,24.95 62.23,32.24 64.22,34.23 64.22,41.72 63.25,42.7 63.25,47 64.82,48.57 64.82,49.5 64.82,49.5 64.82,51.21 65.78,52.18 65.78,55.13 63.91,57 62.89,57 62.8,56.91 61.84,56.91 61.74,57 60.35,57 60.26,56.91 59.17,56.91 59.08,57 57.94,57 57.85,56.91 56.76,56.91 56.66,57 55.15,57 55.05,56.91 54.09,56.91 54,57 52.45,57 52.35,56.91 51.71,56.91 51.62,57 47.65,57 47.56,56.91 46.34,56.91 46.25,57 45.21,57 45.06,56.85 42.55,56.85 J2.2
PTD16: length 64.5
  TOP w0.16: R655.2 v1(61.05,23.91)
  L3_MIX w0.16: J2.4 40.35,57.19 44.92,57.19 45.07,57.34 46.67,57.34 46.77,57.25 47.13,57.25 47.23,57.34 51.76,57.34 51.85,57.25 52.21,57.25 52.31,57.34 54.3,57.34 54.39,57.25 54.75,57.25 54.85,57.34 56.83,57.34 56.93,57.25 57.68,57.25 57.77,57.34 59.38,57.34 59.47,57.25 59.83,57.25 59.93,57.34 62.04,57.34 62.14,57.25 62.5,57.25 62.59,57.34 63.77,57.34 63.77,57.34 64.05,57.34 66.12,55.27 66.12,52.04 65.16,51.07 65.16,49.36 65.15,49.36 65.15,48.31 63.59,46.75 63.59,42.84 64.36,42.06 64.56,41.86 64.56,34.09 62.57,32.1 62.57,24.81 62.45,24.69 62.45,24.68 61.68,23.91 v1(61.05,23.91)
PTD17: length 38.1
  TOP w0.16: U35.20 67.66,25.69 v1(76.92,25.69)
  L3_MIX w0.16: J6.13 76.16,40.81 77.6,39.36 77.6,31.07 76.63,30.1 76.63,25.98 v1(76.92,25.69)
PTE0: length 75.2
  TOP w0.16: U35.94 72.37,39.81 72.73,40.17 v1(72.73,41.19)
  L3_MIX w0.16: J3.6 34.12,3.72 36.54,3.72 36.98,4.16 36.98,16.23 40.43,19.68 40.43,24.23 40.08,24.58 40.08,27.58 43.4,30.9 43.4,32.8 44.67,34.07 v1(44.67,35.73)
  BOTTOM w0.16: v1(44.67,35.73) 48.98,35.73 51.02,37.76 56.22,37.76 60.54,42.08 71.84,42.08 v1(72.73,41.19)
PTE1: length 61.4
  TOP w0.16: U35.93 72.87,35.21 v1(72.99,35.09)
  L3_MIX w0.16: J5.14 90.13,3.85 90.13,6.64 91.45,7.96 91.45,11.53 94.64,14.72 94.64,28.42 97.47,31.25 v1(97.47,32.8)
  BOTTOM w0.16: v1(97.47,32.8) 94.7,32.8 93.83,33.68 87.45,33.68 87.33,33.55 74.14,33.55 72.99,34.71 v1(72.99,35.09)
PTE2: length 49.4
  TOP w0.16: U35.85 76.87,38.21 77.77,39.11 v1(77.77,40.47)
  L3_MIX w0.16: v1(77.77,40.47) 77.94,40.29 77.94,30.93 76.97,29.96 76.97,26.41 77.48,25.9 77.48,20.48 76.97,19.98 76.97,17.23 76.42,16.67 v1(76.42,7.53)
  BOTTOM w0.16: v1(76.42,7.53) 75.76,6.88 67.76,6.88 J4.13
PTE3: length 56.1
  TOP w0.16: U35.18 66.49,26.66 65.88,26.05 v1(65.42,26.05)
  L3_MIX w0.16: v1(65.42,26.05) 66.17,26.8 66.17,43.68 65.83,44.02 65.83,49.08 65.83,49.08 65.83,50.79 66.8,51.76 66.8,54.3 67.1,54.6 67.1,56.47 v1(67.02,56.55)
  BOTTOM w0.16: v1(67.02,56.55) 65.23,56.55 64.6,57.19 46.95,57.19 J1.16
PTE4: length 26.4
  TOP w0.16: R658.2 v1(63.27,35.34)
  L3_MIX w0.16: v1(64.86,54.9) 65.45,54.31 65.45,52.32 64.48,51.35 64.48,49.64 64.48,49.64 64.48,48.71 62.91,47.14 62.91,42.56 63.84,41.63 63.84,35.85 63.33,35.34 v1(63.27,35.34)
  BOTTOM w0.16: J6.20 67.53,54.9 v1(64.86,54.9)
PTE5: length 26.4
  TOP w0.16: R659.2 v1(60.54,37)
  L3_MIX w0.16: v1(60.54,37) 61.43,37.88 61.43,38.77 62.32,39.66 62.32,42.11 62.24,42.19 62.24,47.85 64.14,49.76 64.14,49.78 64.14,49.78 64.14,51.49 64.99,52.34 v1(64.99,53.76)
  BOTTOM w0.16: J6.18 69.68,54.52 68.03,54.52 67.27,53.76 v1(64.99,53.76)
PTE6: length 54.4
  TOP w0.16: U35.84 77.37,38.23 79.71,40.57 v1(81.1,40.57)
  L3_MIX w0.16: v1(81.62,8.04) 80.23,9.44 80.23,18.2 81.84,19.81 81.84,34.11 81.1,34.85 v1(81.1,40.57)
  BOTTOM w0.16: J4.15 69.96,6.54 76.31,6.54 77.81,8.04 v1(81.62,8.04)
PTE7: length 80.8
  TOP w0.16: U35.59 82.07,27.16 81.88,26.96 v1(78.38,26.96) ; J2.14 27.58,54.71 27.58,53.18 30.56,50.2 38.2,50.2 39.22,49.19 71.9,49.19 72.52,48.57 75.76,48.57 v1(76.8,47.54)
  L3_MIX w0.16: v1(78.38,26.96) 78.38,28.71 78.3,28.8 78.3,46.04 v1(76.8,47.54)
PTE8: length 76.4
  TOP w0.16: v1(60,51.44) 45.97,51.44 42.63,54.78 35.14,54.78 J2.8 ; U35.26 68.83,21.41 65.75,18.33 64.35,18.33 62.74,16.72 61.56,16.72 v1(61.52,16.68) 61.52,16.48 R135.2
  L3_MIX w0.16: v1(60,51.44) 59.52,50.96 59.52,36.36 61.56,34.33 61.56,25.23 61.37,25.05 60.58,25.05 60.11,24.58 59.91,24.39 59.91,18.29 v1(61.52,16.68)
PTE9: length 39
  TOP w0.16: R660.2 61.18,17.44 60.29,16.55 59.14,16.55 59.02,16.68 51.9,16.68 50.51,15.28 50.51,12.61 50.13,12.23 50.13,9.94 47.21,7.02 47.21,2.32 46.38,1.49 36.61,1.49 J3.8
PTE10: length 12
  TOP w0.16: U35.6 66.79,32.66 66.25,33.19 66.25,38.23 65.2,39.28 R567.1 R543.2
PTE11: length 9.7
  TOP w0.16: R568.1 R544.2 65.37,39.92 66.59,38.7 66.59,33.37 66.8,33.16 U35.5
PTE12: length 43.7
  TOP w0.16: U35.19 66.55,26.16 65.58,25.18 64.48,25.18 v1(63.97,25.69) ; J6.15 72.41,54.59 67.83,54.59 v1(66.64,55.79)
  L3_MIX w0.16: v1(63.97,25.69) 63.97,26.15 63.96,26.16 63.96,32.03 65.83,33.9 65.83,43.51 65.49,43.85 65.49,49.22 65.49,49.22 65.49,50.93 66.46,51.9 66.46,54.6 66.64,54.78 v1(66.64,55.79)
PTE13: length 61.4
  TOP w0.16: R661.2 v1(63.08,37.63)
  L3_MIX w0.16: J5.8 80.1,3.72 80.1,5.75 81.24,6.9 81.85,6.9 81.85,6.99 84.67,9.82 84.67,9.85 84.84,10.01 84.84,16.62 85.52,17.3 85.52,23.62 86.07,24.17 86.07,36.49 v1(85.94,36.61)
  BOTTOM w0.16: v1(63.08,37.63) 63.46,37.63 63.88,37.21 84.31,37.21 84.91,36.61 v1(85.94,36.61)
PTE14: length 35.2
  TOP w0.16: v1(77.43,26.84) 77.11,27.16 U35.17
  L3_MIX w0.16: v1(77.43,26.84) 77.81,26.45 77.81,20.34 77.5,20.03 77.5,18.34 77.89,17.95 77.89,9.39 77.62,9.12 77.62,3.66 J5.6
PTE15: length 40.6
  TOP w0.16: v1(74.13,34.58) 74.05,34.5 70.65,34.5 70.5,34.66 U35.2
  L3_MIX w0.16: v1(74.13,34.58) 74.13,24.04 73.83,23.74 73.83,17.73 73.62,17.52 73.62,15.02 72.99,14.39 72.99,12.96 72.78,12.75 72.78,8.03 74.89,5.91 74.89,3.85 J5.4
PTE16: length 38.2
  TOP w0.16: U35.1 71.24,35.16 v1(71.59,35.16)
  L3_MIX w0.16: J5.2 72.22,3.98 72.22,6.37 71.59,7 71.59,12.74 72.23,13.38 72.23,17.92 72.61,18.3 72.61,22.14 71.59,23.15 v1(71.59,35.16)
RGB_BLUE: length 78
  TOP w0.16: R156.2 v1(68.8,40.17) ; R603.1 TPAD97.1 106.9,7.91 106.13,8.67 105.85,8.67 105.64,8.88 105.35,8.88 105.06,9.18 88.96,9.18 88.37,8.59 84.79,8.59 84.51,8.87 83.1,8.87 82.79,9.18 73.43,9.18 73.13,8.88 70.24,8.88 v1(69.94,9.18)
  L3_MIX w0.16: v1(69.94,9.18) 69.94,11.98 70.19,12.23 70.19,17.47 71.23,18.5 71.4,18.5 71.67,18.77 71.67,21.45 70.45,22.67 70.45,38.52 v1(68.8,40.17)
RGB_GREEN: length 68.6
  TOP w0.16: R601.1 TPAD95.1 108.67,5.37 105.5,8.55 105.21,8.55 104.92,8.84 89.1,8.84 88.51,8.25 84.65,8.25 84.37,8.54 82.96,8.54 82.65,8.84 73.57,8.84 73.27,8.55 65.11,8.55 v1(64.35,9.31) ; R155.2 v1(61.05,22.9)
  L3_MIX w0.16: v1(61.05,22.9) 61.56,22.39 61.56,18.27 62.74,17.08 62.74,15.76 61.64,14.66 61.64,10.4 62.73,9.31 v1(64.35,9.31)
RGB_RED: length 68.5
  TOP w0.16: R154.2 v1(61.05,20.87) ; R598.1 TPAD94.1 110.2,3.09 104.78,8.51 89.24,8.51 88.65,7.91 84.51,7.91 84.23,8.2 82.82,8.2 82.51,8.51 73.71,8.51 73.37,8.17 v1(64.35,8.17)
  L3_MIX w0.16: v1(61.05,20.87) 61.05,18.3 62.4,16.94 62.4,15.9 61.3,14.8 61.3,9.06 62.19,8.17 v1(64.35,8.17)
RST_TGTMCU_B: length 187.3
  TOP w0.16: R585.2 44.28,25.95 v1(44.41,26.07) ; D1.C 4.02,52.08 v1(4.52,51.58) R4.2 ; U35.97 70.87,39.62 68.58,41.91 v1(68.58,44.62) ; v1(12.41,12.76) 12.41,12.11 12.02,11.72 12.02,7.14 13.12,6.05 24.18,6.05 26.38,3.85 31.71,3.85 J3.5 34.25,3.85 46.06,3.85 46.82,4.61 46.82,8.42 45.3,9.94 v1(44.41,9.94) ; J14.10 50.37,44.37 50,44.74 50,45.12 R574.2 49.24,46.39 48.6,47.03 v1(46.44,47.03)
  TOP w0.203: TP539.1 4.03,54.29 4.02,54.29 D1.C ; J104.3 12.15,48.91 11.8,49.26 R5.2 ; U1.7 v1(7.71,48.81)
  TOP w0.508: v1(68.58,44.62) 68.58,45.26 67.95,45.89 TS7.1
  L3_MIX w0.16: v1(44.41,9.94) 43.9,10.45 43.9,11.1 44.31,11.52 44.48,11.52 44.75,11.79 44.75,25.74 v1(44.41,26.07) 45.6,27.26 45.6,32.34 46.44,33.19 v1(46.44,47.03)
  BOTTOM w0.16: v1(68.58,44.62) 67.83,45.38 52.89,45.38 J14.10 ; v1(12.41,12.76) 10.99,12.76 7.45,16.29 7.45,23.53 6.06,24.93 6.06,46.14 6.31,46.39
  BOTTOM w0.203: J104.3 9.21,47.79 8.19,48.81 v1(7.71,48.81) ; v1(7.71,48.81) 6.31,47.41 6.31,46.39 ; v1(7.71,48.81) 7.71,50 7.51,50.2 5.9,50.2 v1(4.52,51.58)
SBC_CAN_RX: length 22.5
  TOP w0.16: R588.2 v1(50.89,26.07) ; R137.2 v1(63.27,36.36)
  L3_MIX w0.16: v1(50.89,26.07) 53.14,28.32 53.14,34.04 v1(53.17,34.07)
  BOTTOM w0.16: v1(53.17,34.07) 53.43,34.33 53.43,35.98 53.81,36.36 v1(63.27,36.36)
SBC_CAN_RX_LS: length 35.3
  TOP w0.16: v1(50.13,17.56) 50.51,17.95 TP512.1 R580.1
  TOP w0.305: U19.7 21.07,18.74 21.1,18.71 21.54,18.71 21.58,18.74 21.59,18.74 v1(21.68,18.83)
  BOTTOM w0.203: v1(50.13,17.56) 50.13,18.05 49.09,19.09 47.08,19.09 46.19,18.2 43.65,18.2 42.51,17.06 38.09,17.06 36.06,19.09 25.13,19.09 25.11,19.11 24.35,19.11 24.07,18.83 v1(21.68,18.83)
SBC_CAN_TX: length 24.3
  TOP w0.16: R136.2 v1(60.54,38.01) ; R587.2 v1(49.87,26.07)
  L3_MIX w0.16: v1(50,35.09) 52.33,32.76 52.33,28.66 49.87,26.2 v1(49.87,26.07)
  BOTTOM w0.16: v1(50,35.09) 50.89,35.98 51.9,35.98 53.01,37.08 56.5,37.08 56.54,37.12 56.6,37.12 57.49,38.01 v1(60.54,38.01)
SBC_CAN_TX_LS: length 33.6
  TOP w0.16: R579.1 TP513.1 48.48,18.96 v1(48.86,18.58)
  TOP w0.305: v1(21.17,15.53) 21.17,15.79 20.72,16.24 U19.2
  BOTTOM w0.16: v1(21.17,15.53) 21.5,15.86 47.16,15.86 48.86,17.56 v1(48.86,18.58)
SBC_CS: length 68.1
  TOP w0.16: R592.2 v1(41.24,19.85) ; R129.1 v1(91.27,30.77)
  L3_MIX w0.16: v1(91.66,17.44) 91.02,18.07 91.02,18.83 91.62,19.43 91.62,29.44 91.74,29.57 91.74,30.31 v1(91.27,30.77)
  BOTTOM w0.16: v1(91.66,17.44) 91.27,17.82 85.31,17.82 84.42,18.71 79.72,18.71 79.46,18.96 73.75,18.96 72.99,19.72 70.83,19.72 70.32,19.22 68.29,19.22 67.53,18.45 55.97,18.45 55.21,19.22 50.76,19.22 50.38,19.6 41.49,19.6 v1(41.24,19.85)
SBC_CS_LS: length 30.5
  TOP w0.16: v1(14.95,15.53) 15.84,15.53 15.88,15.58 15.9,15.58 16.06,15.74 U19.20 ; v1(40.86,15.02) TP517.1 40.27,16.17 40.14,16.04 R584.1
  BOTTOM w0.16: v1(40.86,15.02) 40.27,15.02 40.14,14.9 20.98,14.9 20.85,15.03 16.98,15.03 16.47,15.53 v1(14.95,15.53)
SBC_LIMP: length 27.7
  TOP w0.16: R532.2 v1(63.08,38.65) ; R586.2 v1(45.3,26.07)
  L3_MIX w0.16: v1(45.3,26.07) 45.94,26.71 45.94,31.79 v1(46.44,32.3)
  BOTTOM w0.16: v1(63.08,38.65) 57.62,38.65 56.48,37.5 56.45,37.5 56.36,37.42 51.16,37.42 48.6,34.87 48.6,34.46 v1(46.44,32.3)
SBC_LIMP_LS: length 36.4
  TOP w0.16: R536.2 15.84,20.61 16.05,20.82 v1(16.58,20.82) U19.11 ; R578.1 TP505.1
  TOP w0.203: TP505.1 v1(46.06,18.78)
  BOTTOM w0.16: v1(16.58,20.82) 19.48,20.82 20,21.34 20.2,21.54 20.51,21.54 20.56,21.59 21.27,21.59 21.32,21.54 34.76,21.54 34.99,21.31 36.1,21.31 36.6,20.8 36.6,20.55 37.05,20.1 37.55,20.1 37.81,19.85 37.81,19.6 38.62,18.78 v1(46.06,18.78)
SBC_MISO: length 71.7
  TOP w0.16: R591.2 v1(37.43,20.61) ; R125.1 v1(91.27,31.92)
  L3_MIX w0.16: v1(91.66,18.71) 91.95,19 91.95,29.3 92.07,29.43 92.07,31.12 v1(91.27,31.92)
  BOTTOM w0.16: v1(37.43,20.61) 41.62,20.61 42.25,19.98 50.54,19.98 50.92,19.6 55.36,19.6 56.13,18.83 67.37,18.83 68.13,19.6 70.16,19.6 70.67,20.1 73.14,20.1 73.91,19.34 79.63,19.34 79.88,19.09 84.57,19.09 85.46,18.2 91.15,18.2 v1(91.66,18.71)
SBC_MISO_LS: length 22.9
  TOP w0.16: v1(35.27,16.93) 35.78,16.42 TP516.1 38.06,16.42 R583.1
  TOP w0.305: v1(20.92,20.74) 20.92,20.21 20.45,19.74 U19.9
  BOTTOM w0.16: v1(20.92,20.74) 20.58,20.41 20.58,18.74 20.79,18.54 20.79,18.46 21.31,17.94 21.38,17.94 21.68,17.64 34.55,17.64 v1(35.27,16.93)
SBC_MOSI: length 53.9
  TOP w0.16: R590.2 v1(40.86,27.47) ; R126.1 v1(88.73,29.76)
  L3_MIX w0.16: v1(88.73,29.76) 88.73,27.85 v1(88.99,27.6)
  BOTTOM w0.16: v1(88.99,27.6) 77.43,27.6 76.42,26.58 66.02,26.58 65.75,26.85 65.09,26.85 64.82,26.58 60.41,26.58 59.4,25.57 45.52,25.57 45.51,25.56 45.09,25.56 45.09,25.57 44.16,25.57 43.52,26.2 42.13,26.2 v1(40.86,27.47)
SBC_MOSI_LS: length 27.3
  TOP w0.16: U19.3 20.97,16.74 v1(21.17,16.54) 21.29,16.42 TP515.1
  TOP w0.203: R582.1 38.44,22.26 39.1,22.26 39.23,22.39 v1(39.71,22.39)
  L3_MIX w0.16: v1(36.16,16.93) 37.09,16.93 39.71,19.55 v1(39.71,22.39)
  BOTTOM w0.16: v1(36.16,16.93) 35.65,16.42 21.82,16.42 21.7,16.54 v1(21.17,16.54)
SBC_RST_LS: length 29.6
  TOP w0.16: R577.1 TP506.1
  TOP w0.203: TP506.1 43.9,17.69 v1(43.65,17.44)
  TOP w0.305: R594.2 21.42,19.85 v1(21.04,19.47) 20.82,19.24 U19.8
  BOTTOM w0.203: v1(21.04,19.47) 21.04,18.79 21.15,18.68 21.15,18.61 21.46,18.3 21.9,18.3 21.93,18.33 24.17,18.33 24.19,18.35 24.19,18.42 24.51,18.73 24.95,18.73 24.97,18.71 35.24,18.71 35.24,18.71 35.78,18.71 37.81,16.68 42.89,16.68 v1(43.65,17.44)
SBC_SCK: length 60.7
  TOP w0.16: R124.1 v1(88.73,31.92) ; R589.2 v1(38.19,27.47)
  L3_MIX w0.16: v1(90,27.09) 90,30.65 89.2,31.45 89.2,31.57 88.86,31.92 v1(88.73,31.92)
  BOTTOM w0.16: v1(90,27.09) 79.21,27.09 78.57,26.45 78.07,26.45 77.86,26.24 65.88,26.24 65.61,26.51 65.23,26.51 64.96,26.24 60.71,26.24 59.7,25.23 45.66,25.23 45.65,25.22 44.95,25.22 44.95,25.23 44.02,25.23 43.82,25.42 43.82,25.43 43.38,25.86 41.99,25.86 41.65,26.2 41.62,26.2 41.36,26.45 39.84,26.45 38.82,27.47 v1(38.19,27.47)
SBC_SCK_LS: length 19.3
  TOP w0.16: U19.10 19.88,21.18 19.65,21.41 v1(19.65,21.88)
  TOP w0.203: R581.1 36.03,22.64 TP514.1 v1(35.14,21.88)
  BOTTOM w0.16: v1(35.14,21.88) 34.63,21.88 34.5,22.01 20.24,22.01 20.11,21.88 v1(19.65,21.88)
SDA_EXTAL: length 5.4
  TOP w0.16: U8.17 20.55,36.2 20.55,34.32 C23.1 21.3,33.58 21.74,33.58 Y1.3
SDA_JTAG_TCLK: length 11.7
  TOP w0.16: J12.4 15.44,29.36 14.29,30.51 14.27,30.51 14,30.78 14,30.8 13.83,30.97 13.83,34.37 U8.12
SDA_JTAG_TDI: length 8.3
  TOP w0.16: U8.13 v1(17.23,37.07)
  BOTTOM w0.16: v1(17.23,37.07) 17.23,36.28 14.64,33.69 14.64,32.68 14.89,32.43 14.91,32.43 15.44,31.9 J12.8
SDA_JTAG_TDO: length 9.4
  TOP w0.16: J12.6 15.44,30.63 14.93,31.14 14.93,31.17 14.66,31.44 14.63,31.44 14.57,31.5 14.57,33.69 U8.14
SDA_JTAG_TMS: length 17.6
  TOP w0.16: U8.15 18.31,36.73 18.31,34.6 20.03,32.88 20.03,27.39 19.45,26.81 17.33,26.81 J12.2 14.69,28.09 14.68,28.08 R77.2
SDA_LED: length 2.7
  TOP w0.16: D2.C 22.74,42.45 21.91,42.45 U8.29
SDA_LED_R: length 1.3
  TOP w0.16: R12.2 24.28,43.99 D2.A
SDA_RST: length 18.4
  TOP w0.16: U8.19 21.16,37.01 TP12.1 24.86,36.59 24.86,36.59 R57.2 25.69,35.76 25.69,35.76 R62.1 26.69,34.76 v1(26.69,34.76)
  BOTTOM w0.16: v1(26.69,34.76) 17.63,34.76 J12.10
SDA_RST_LED: length 1.4
  TOP w0.16: D1.A R2.1
SDA_RST_TGTMCU_B: length 16.7
  TOP w0.16: v1(24.18,38.33) 23.62,37.76 21.83,37.76 U8.21
  BOTTOM w0.16: J105.2 23.33,46.82 23.16,46.65 21.85,46.65 20.63,45.43 20.63,44.7 21.73,43.6 21.73,39.66 23.06,38.33 v1(24.18,38.33)
SDA_RST_TGTMCU_J_B: length 16.2
  TOP w0.16: J105.1 J104.1 17.23,49.06 16.34,49.95 R5.1 12.82,50.52 11.9,51.43 10.18,51.43 R3.2 8.48,51.91 8.11,51.54 U1.2
SDA_RX_EN: length 3.7
  TOP w0.16: v1(32.98,44.62) 32.8,44.43 R16.1 32.02,44.44 R15.2 U4.5
SDA_SPI0_CS: length 9.7
  TOP w0.16: U8.23 22.5,38.5 22.69,38.5 24.23,40.04 25.67,40.04 25.78,40.15 TP7.1 R38.2
SDA_SPI0_RST_B: length 10.1
  TOP w0.16: R41.2 30.48,39.15 30.23,39.4 26.18,39.4 25.93,39.15 TP8.1 24.2,39.15 23.17,38.13 22.17,38.13 U8.22
SDA_SPI0_SCK: length 9.5
  TOP w0.16: v1(27.49,37.09) 27.59,37.19 28.04,37.19 28.48,37.62 U10.3 ; 22.1,40.52 22.63,41.05 v1(25.08,41.05)
  BOTTOM w0.16: v1(25.08,41.05) 25.08,40.04 27.12,38 27.12,37.45 v1(27.49,37.09)
SDA_SPI0_SIN: length 11
  TOP w0.16: U8.28 22.12,41.95 23.59,41.95 27.19,45.54 27.19,47.52 v1(27.52,47.85) U2.5
SDA_SPI0_SOUT: length 7.5
  TOP w0.16: U7.3 27.3,40.66 26.4,41.56 v1(23.99,41.56) 22.44,41.56 U8.27
SDA_SWD_EN: length 2.5
  TOP w0.16: R41.1 R47.1 33.88,39.15 34.03,39.3 U9.6
SDA_SWD_EN_B: length 19.4
  TOP w0.16: U8.16 v1(19.63,36.21) ; v1(35.58,38.7) R49.2
  BOTTOM w0.16: v1(35.58,38.7) 35.58,38.11 33.09,35.62 26.2,35.62 25.61,36.21 v1(19.63,36.21)
